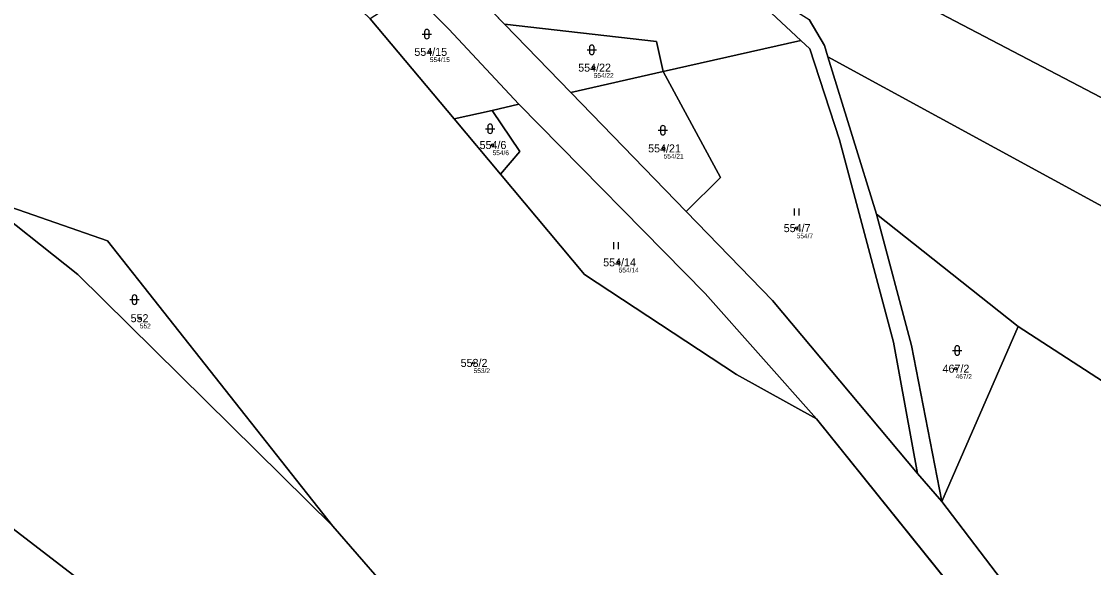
# Model space of a CAD drawing. Extents: x -766177 to -763254, y -1057727 to -1053915.
# Drawn here: x -765322 to -765094.3, y -1055503.5 to -1055387.6 of the extents above; entities that cross this region are included whole.
import ezdxf

# ---------------------------------------------------------------- set-up
doc = ezdxf.new("R2010")
doc.units = 0
for name, color, linetype in [('Vrstva 1', 7, 'Continuous'), ('Vrstva 2', 7, 'Continuous'), ('Vrstva 3', 7, 'Continuous'), ('Vrstva 50', 7, 'Continuous'), ('Vrstva 51', 7, 'Continuous')]:
    doc.layers.add(name, color=color, linetype=linetype)

msp = doc.modelspace()

# ---------------------------------------------------------------- linework, layer by layer
at = {"layer": 'Vrstva 1'}
for p, q in [((-765241.56, -1055365.33), (-765219.42, -1055388.14)), ((-765230.11, -1055408.28), (-765247.92, -1055387.04)), ((-765219.42, -1055388.14), (-765205.3, -1055402.69)), ((-765156.47, -1055391.61), (-765185.72, -1055398.25)), ((-765150.71, -1055395.09), (-765140.42, -1055428.53)), ((-765185.72, -1055398.25), (-765205.3, -1055402.69)), ((-765205.3, -1055402.69), (-765180.82, -1055427.96)), ((-765216.35, -1055405.18), (-765222.01, -1055406.46)), ((-765222.01, -1055406.46), (-765230.11, -1055408.28)), ((-765220.28, -1055420), (-765230.11, -1055408.28)), ((-765140.42, -1055428.53), (-765110.33, -1055452.36)), ((-765110.33, -1055452.36), (-765126.57, -1055489.53)), ((-765100.14, -1055537.81), (-765153.18, -1055471.96)), ((-765131.69, -1055483.57), (-765126.57, -1055489.53))]:
    msp.add_line(p, q, dxfattribs=at)
for points in [[(-765156.47, -1055391.61), (-765165.79, -1055382.88), (-765187.34, -1055343.83)], [(-765216.35, -1055405.18), (-765231.24, -1055389.24), (-765251.22, -1055369.1)], [(-765160.62, -1055368.14), (-764948, -1055479.38), (-764883.67, -1055494.44), (-764811.91, -1055508.77), (-764753.73, -1055525)], [(-765161.73, -1055382.7), (-765154.68, -1055387.18), (-765151.44, -1055392.72), (-765150.71, -1055395.09)], [(-765185.72, -1055398.25), (-765187.1, -1055391.87), (-765219.42, -1055388.14)], [(-765131.69, -1055483.57), (-765136.82, -1055455.71), (-765148.24, -1055412.74), (-765154.58, -1055393.38), (-765156.47, -1055391.61)], [(-765150.71, -1055395.09), (-765021.52, -1055465.51), (-764966.65, -1055489.05), (-764951.49, -1055500.21), (-764771.73, -1055542.36), (-764763.19, -1055547.21)], [(-765185.72, -1055398.25), (-765173.51, -1055420.7), (-765180.82, -1055427.96)], [(-765153.18, -1055471.96), (-765176.8, -1055445.35), (-765216.35, -1055405.18)], [(-765220.28, -1055420), (-765216.12, -1055415.23), (-765222.01, -1055406.46)], [(-765153.18, -1055471.96), (-765170.15, -1055462.56), (-765202.41, -1055441.32), (-765220.28, -1055420)], [(-765255.86, -1055494.74), (-765310, -1055441.31), (-765331.11, -1055424.6)], [(-765255.86, -1055494.74), (-765303.74, -1055434.19), (-765324.25, -1055427)], [(-765180.82, -1055427.96), (-765162.52, -1055446.85), (-765131.69, -1055483.57)], [(-765140.42, -1055428.53), (-765133.01, -1055456.37), (-765126.57, -1055489.53)], [(-765110.33, -1055452.36), (-765062.6, -1055483.25), (-765042.11, -1055496.97), (-765013.65, -1055517.61)], [(-765232.98, -1055590.19), (-765250.05, -1055566.44), (-765274.23, -1055539.71), (-765306.57, -1055508.53), (-765329.33, -1055491.07), (-765359.95, -1055472.19)], [(-765126.57, -1055489.53), (-765049.17, -1055591.02), (-764946.91, -1055733.8)], [(-765198.32, -1055571.53), (-765230.05, -1055524.46), (-765255.86, -1055494.74)]]:
    msp.add_lwpolyline(points, dxfattribs=at)
at = {"layer": 'Vrstva 3'}
for p, q in [((-765236.891, -1055390.281), (-765234.889, -1055390.281)), ((-765236.391, -1055389.781), (-765236.391, -1055390.782)), ((-765235.389, -1055390.782), (-765235.389, -1055389.781)), ((-765201.861, -1055393.621), (-765199.859, -1055393.621)), ((-765201.361, -1055393.121), (-765201.361, -1055394.122)), ((-765200.359, -1055394.122), (-765200.359, -1055393.121)), ((-765222.951, -1055409.871), (-765222.951, -1055410.872)), ((-765221.949, -1055410.872), (-765221.949, -1055409.871)), ((-765186.261, -1055410.181), (-765186.261, -1055411.182)), ((-765185.259, -1055411.182), (-765185.259, -1055410.181)), ((-765223.451, -1055410.371), (-765221.449, -1055410.371)), ((-765186.761, -1055410.681), (-765184.759, -1055410.681)), ((-765157.811, -1055428.82), (-765157.811, -1055427.32)), ((-765156.81, -1055428.82), (-765156.81, -1055427.32)), ((-765196.191, -1055435.92), (-765196.191, -1055434.42)), ((-765195.19, -1055435.92), (-765195.19, -1055434.42)), ((-765298.471, -1055446.151), (-765298.471, -1055447.152)), ((-765297.469, -1055447.152), (-765297.469, -1055446.151)), ((-765298.971, -1055446.651), (-765296.969, -1055446.651)), ((-765124.281, -1055457.441), (-765122.279, -1055457.441)), ((-765123.781, -1055456.941), (-765123.781, -1055457.942)), ((-765122.779, -1055457.942), (-765122.779, -1055456.941))]:
    msp.add_line(p, q, dxfattribs=at)
for centre, start, end in [((-765235.89, -1055389.7809), 0, 180), ((-765235.89, -1055390.7809), 180, 359.9878861), ((-765200.86, -1055393.1209), 0, 180), ((-765200.86, -1055394.1209), 180, 359.9878861), ((-765222.45, -1055409.8709), 0, 180), ((-765185.76, -1055410.1809), 0, 180), ((-765222.45, -1055410.8709), 180, 359.9878861), ((-765185.76, -1055411.1809), 180, 359.9878861), ((-765297.97, -1055446.1509), 0, 180), ((-765297.97, -1055447.1509), 180, 359.9878861), ((-765123.28, -1055456.9409), 0, 180), ((-765123.28, -1055457.9409), 180, 359.9878861)]:
    msp.add_arc(centre, 0.5, start, end, dxfattribs=at)
at = {"layer": 'Vrstva 50'}
for centre in [(-765235.24, -1055394.04994), (-765200.45, -1055397.39994), (-765221.92, -1055413.81994), (-765185.6, -1055414.53994), (-765157.34, -1055431.46994), (-765195.15, -1055438.72994), (-765296.82, -1055450.58994), (-765225.94, -1055460.07994), (-765123.61, -1055461.29994)]:
    msp.add_circle(centre, 0.25, dxfattribs=at)
at = {"layer": 'Vrstva 51'}
for points in [[(-765423.35, -1055181.09), (-765411.93, -1055189.52), (-765384.32, -1055193.44), (-765369.69, -1055207.08), (-765362.68, -1055211.26), (-765353.56, -1055222.85), (-765342.75, -1055241.37), (-765331.26, -1055272.17), (-765324.7, -1055283.27), (-765307.37, -1055300.27), (-765298.27, -1055311.36), (-765283.75, -1055336.44), (-765271.8, -1055348.99), (-765265, -1055355.64), (-765251.22, -1055369.1), (-765231.24, -1055389.24), (-765216.35, -1055405.18), (-765176.8, -1055445.35), (-765153.18, -1055471.96), (-765100.14, -1055537.81), (-765011.4, -1055660.75), (-764958.56, -1055733.66)], [(-764873.17, -1055832.33), (-764905.37, -1055788.34), (-764943.29, -1055738.6), (-764946.91, -1055733.8), (-765049.17, -1055591.02), (-765126.57, -1055489.53), (-765131.69, -1055483.57), (-765162.52, -1055446.85), (-765180.82, -1055427.96), (-765205.3, -1055402.69), (-765219.42, -1055388.14), (-765241.56, -1055365.33), (-765267.92, -1055338.31), (-765276.08, -1055328.95), (-765279.28, -1055323.38), (-765284.28, -1055314.72), (-765299.66, -1055294.43), (-765309.67, -1055283.82), (-765320.99, -1055267.62), (-765333.31, -1055236.33), (-765341.99, -1055216.69), (-765350.07, -1055205.63), (-765357.57, -1055198.12)], [(-765165.79, -1055382.88), (-765156.47, -1055391.61), (-765154.58, -1055393.38), (-765148.24, -1055412.74), (-765136.82, -1055455.71), (-765131.69, -1055483.57), (-765126.57, -1055489.53), (-765133.01, -1055456.37), (-765140.42, -1055428.53), (-765150.71, -1055395.09), (-765151.44, -1055392.72), (-765154.68, -1055387.18)]]:
    msp.add_lwpolyline(points, dxfattribs=at)
for points in [[(-765100.14, -1055537.81), (-765153.18, -1055471.96), (-765170.15, -1055462.56), (-765202.41, -1055441.32), (-765220.28, -1055420), (-765230.11, -1055408.28), (-765247.92, -1055387.04), (-765261.96, -1055373.52), (-765270.29, -1055365.49), (-765291.85, -1055345.3), (-765305.46, -1055330.15), (-765320.09, -1055329.75), (-765330.73, -1055334.55), (-765332.48, -1055348.25), (-765324.25, -1055427), (-765303.74, -1055434.19), (-765255.86, -1055494.74), (-765230.05, -1055524.46), (-765198.32, -1055571.53), (-765188.41, -1055587.44)], [(-765165.79, -1055382.88), (-765187.34, -1055343.83), (-765241.56, -1055365.33), (-765219.42, -1055388.14), (-765187.1, -1055391.87), (-765185.72, -1055398.25), (-765156.47, -1055391.61)], [(-764743.22, -1055501.86), (-764938.76, -1055452.8), (-764970.17, -1055440.01), (-764994.42, -1055428.64), (-765047.37, -1055402.44), (-765159.08, -1055347.83), (-765160.62, -1055368.14), (-764948, -1055479.38), (-764883.67, -1055494.44), (-764811.91, -1055508.77), (-764753.73, -1055525)], [(-765244.15, -1055384.65), (-765247.92, -1055387.04), (-765230.11, -1055408.28), (-765222.01, -1055406.46), (-765216.35, -1055405.18), (-765231.24, -1055389.24), (-765251.22, -1055369.1), (-765256.93, -1055371.45)], [(-765021.52, -1055465.51), (-764966.65, -1055489.05), (-764951.49, -1055500.21), (-764771.73, -1055542.36), (-764763.19, -1055547.21), (-764753.73, -1055525), (-764811.91, -1055508.77), (-764883.67, -1055494.44), (-764948, -1055479.38), (-765160.62, -1055368.14), (-765161.73, -1055382.7), (-765154.68, -1055387.18), (-765151.44, -1055392.72), (-765150.71, -1055395.09)], [(-765185.72, -1055398.25), (-765187.1, -1055391.87), (-765219.42, -1055388.14), (-765205.3, -1055402.69)], [(-765156.47, -1055391.61), (-765185.72, -1055398.25), (-765173.51, -1055420.7), (-765180.82, -1055427.96), (-765162.52, -1055446.85), (-765131.69, -1055483.57), (-765136.82, -1055455.71), (-765148.24, -1055412.74), (-765154.58, -1055393.38)], [(-764903.01, -1055588.69), (-764809.7, -1055612.56), (-764805.97, -1055607.73), (-764779.33, -1055585.09), (-764763.19, -1055547.21), (-764771.73, -1055542.36), (-764951.49, -1055500.21), (-764966.65, -1055489.05), (-765021.52, -1055465.51), (-765150.71, -1055395.09), (-765140.42, -1055428.53), (-765110.33, -1055452.36), (-765062.6, -1055483.25), (-765042.11, -1055496.97), (-765013.65, -1055517.61), (-764991.48, -1055541.73), (-764962.27, -1055567.03), (-764925.71, -1055587.46)], [(-765185.72, -1055398.25), (-765205.3, -1055402.69), (-765180.82, -1055427.96), (-765173.51, -1055420.7)], [(-765176.8, -1055445.35), (-765216.35, -1055405.18), (-765222.01, -1055406.46), (-765216.12, -1055415.23), (-765220.28, -1055420), (-765202.41, -1055441.32), (-765170.15, -1055462.56), (-765153.18, -1055471.96)], [(-765255.86, -1055494.74), (-765310, -1055441.31), (-765331.11, -1055424.6), (-765360.28, -1055405.9), (-765359.95, -1055472.19), (-765329.33, -1055491.07), (-765306.57, -1055508.53), (-765274.23, -1055539.71), (-765250.05, -1055566.44), (-765232.98, -1055590.19), (-765228.25, -1055596.6), (-765198.32, -1055571.53), (-765230.05, -1055524.46)], [(-765216.12, -1055415.23), (-765222.01, -1055406.46), (-765230.11, -1055408.28), (-765220.28, -1055420)], [(-765255.86, -1055494.74), (-765303.74, -1055434.19), (-765324.25, -1055427), (-765331.11, -1055424.6), (-765310, -1055441.31)], [(-765133.01, -1055456.37), (-765126.57, -1055489.53), (-765110.33, -1055452.36), (-765140.42, -1055428.53)], [(-764917.06, -1055711.83), (-764910.86, -1055706.2), (-764991.37, -1055637.93), (-765041.12, -1055553.95), (-765019.38, -1055529.01), (-765013.65, -1055517.61), (-765042.11, -1055496.97), (-765062.6, -1055483.25), (-765110.33, -1055452.36), (-765126.57, -1055489.53), (-765049.17, -1055591.02), (-764946.91, -1055733.8), (-764929.13, -1055719.16)], [(-765329.33, -1055491.07), (-765359.95, -1055472.19), (-765366.17, -1055469.23), (-765366.84, -1055508.39), (-765335.16, -1055532.2), (-765279.39, -1055594.13), (-765232.98, -1055590.19), (-765250.05, -1055566.44), (-765274.23, -1055539.71), (-765306.57, -1055508.53)]]:
    msp.add_lwpolyline(points, close=True, dxfattribs=at)

# ---------------------------------------------------------------- texts
at = {"layer": 'Vrstva 2'}
for s, p in [('554/15', (-765238.545, -1055394.9)), ('554/22', (-765203.755, -1055398.25)), ('554/6', (-765224.693, -1055414.67)), ('554/21', (-765188.905, -1055415.39)), ('554/7', (-765160.113, -1055432.32)), ('554/14', (-765198.455, -1055439.58)), ('552', (-765298.794, -1055451.44)), ('553/2', (-765228.713, -1055460.93)), ('467/2', (-765126.383, -1055462.15))]:
    msp.add_text(s, height=1.699998, dxfattribs=at).set_placement(p)
at = {"layer": 'Vrstva 50'}
for s, p in [('554/15', (-765235.24, -1055396.206)), ('554/22', (-765200.45, -1055399.556)), ('554/6', (-765221.92, -1055415.976)), ('554/21', (-765185.6, -1055416.696)), ('554/7', (-765157.34, -1055433.626)), ('554/14', (-765195.15, -1055440.886)), ('552', (-765296.82, -1055452.746)), ('553/2', (-765225.94, -1055462.236)), ('467/2', (-765123.61, -1055463.456))]:
    msp.add_text(s, height=0.999996, dxfattribs=at).set_placement(p)

doc.saveas('drawing.dxf')
